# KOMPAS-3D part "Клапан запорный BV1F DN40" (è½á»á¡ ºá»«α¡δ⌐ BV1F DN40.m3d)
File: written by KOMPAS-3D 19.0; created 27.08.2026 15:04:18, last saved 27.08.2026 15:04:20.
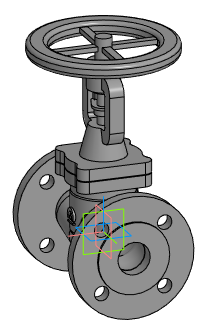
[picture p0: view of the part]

Document properties: Автор: Энергия; Полное имя файла: E:\Dendor\_3D для проектировщиков\5.6 Клапан запорный BV1F\stp\Клапан запорный BV1F DN40.m3d

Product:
- Part/product: Клапан запорный BV1F DN40
    Масса: 12.6896

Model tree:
1. Операция без истории:1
